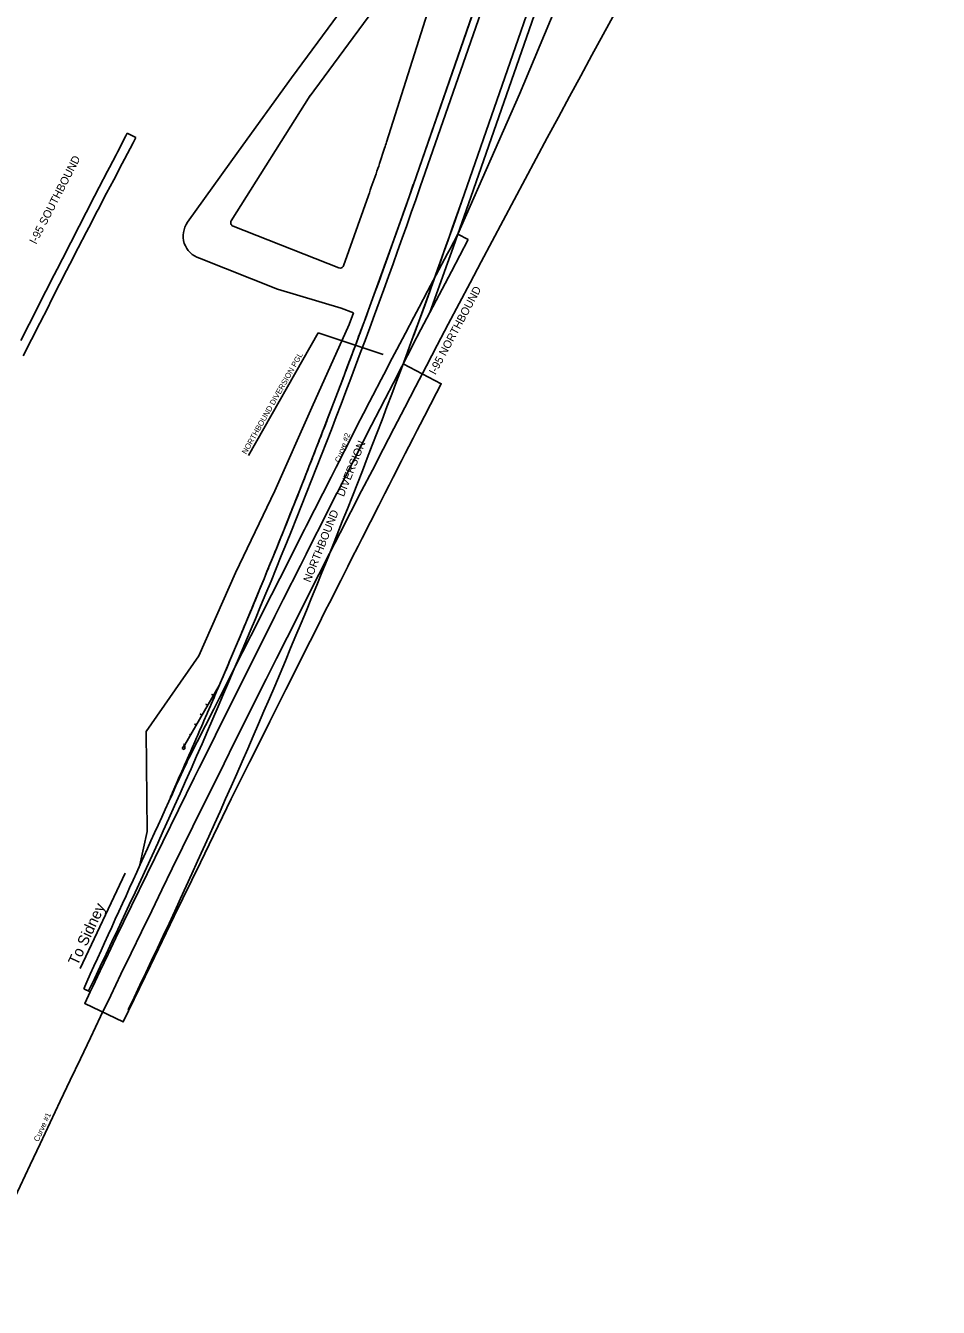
# Model space of a CAD drawing. Extents: x 1160458 to 1162290, y 615427 to 618737.
# Drawn here: x 1160710 to 1161210, y 615879 to 616580 of the extents above; entities that cross this region are included whole.
import ezdxf

# ---------------------------------------------------------------- set-up
doc = ezdxf.new("R2010")
doc.units = 0
for name, color, linetype in [('1', 7, 'Continuous'), ('ANNOTATION', 7, 'Continuous'), ('D_Drainage_Ditch_Line', 7, 'Continuous'), ('D_Guardrail_Beam_Lt', 7, 'Continuous'), ('D_Guardrail_End_MELT', 7, 'Continuous'), ('D_Roadway_Edge_Pavement', 7, 'Continuous'), ('D_Roadway_Edge_Shoulder', 7, 'Continuous'), ('D_Roadway_Edge_TW', 7, 'Continuous'), ('D_Slope_Cut', 7, 'Continuous'), ('D_Slope_Fill', 7, 'Continuous'), ('D_Text_Standard', 7, 'Continuous'), ('Old pavement area_not used', 7, 'Continuous'), ('Shoulder work for div plan (NB)', 7, 'Continuous'), ('Shoulder work for div plans (SB)', 7, 'Continuous')]:
    doc.layers.add(name, color=color, linetype=linetype)

msp = doc.modelspace()

# ---------------------------------------------------------------- linework, layer by layer
at = {"layer": '1'}
msp.add_arc((1171291.23, 610981.4), 11690.13, 149.585749, 157.64029, dxfattribs=at)
at = {"layer": 'D_Drainage_Ditch_Line'}
for p, q in [((1160865.58, 616541.07), (1160946.69, 616651.23)), ((1160822.97, 616473.58), (1160866.18, 616541.95)), ((1160881.78, 616447.76), (1160823.93, 616470.65))]:
    msp.add_line(p, q, dxfattribs=at)
msp.add_lwpolyline([(1160950.21, 616649.43), (1160936.96, 616608.03), (1160936.24, 616605.79), (1160907.92, 616516.58), (1160907.66, 616515.75), (1160907.4, 616514.93), (1160907.13, 616514.12), (1160906.87, 616513.29), (1160904.13, 616504.89), (1160903.65, 616503.46), (1160903.18, 616502.05), (1160902.69, 616500.64), (1160902.19, 616499.21), (1160900.09, 616493.32), (1160899.57, 616491.83), (1160899.04, 616490.35), (1160898.51, 616488.87), (1160897.99, 616487.38), (1160884.4, 616448.95)], dxfattribs=at)
for centre, start, end in [((1160824.66, 616472.51), 147.7107, 248.40964), ((1160882.51, 616449.62), 248.40964, 340.52546)]:
    msp.add_arc(centre, 2, start, end, dxfattribs=at)
at = {"layer": 'D_Guardrail_Beam_Lt'}
msp.add_line((1160966.79, 616620.56), (1160922.58, 616493.37), dxfattribs=at)
for start, end in [(337.73067, 340.83052), (336.81172, 337.73067)]:
    msp.add_arc((1156970.57, 617867.25), 4184, start, end, dxfattribs=at)
at = {"layer": 'D_Guardrail_End_MELT'}
for p, q in [((1160816.43, 616219.44), (1160797.64, 616186.98)), ((1160812.55, 616214.74), (1160812.3, 616214.31)), ((1160812.86, 616214.28), (1160812.43, 616214.53)), ((1160812.99, 616214.49), (1160812.74, 616214.06)), ((1160813.29, 616214.03), (1160812.86, 616214.28)), ((1160809.42, 616209.33), (1160809.17, 616208.9)), ((1160809.73, 616208.87), (1160809.3, 616209.12)), ((1160809.86, 616209.08), (1160809.61, 616208.65)), ((1160810.16, 616208.62), (1160809.73, 616208.87)), ((1160806.29, 616203.93), (1160806.04, 616203.49)), ((1160806.6, 616203.46), (1160806.17, 616203.71)), ((1160806.73, 616203.68), (1160806.47, 616203.24)), ((1160807.03, 616203.21), (1160806.6, 616203.46)), ((1160800.46, 616192.86), (1160800.21, 616192.42)), ((1160803.16, 616198.52), (1160802.91, 616198.08)), ((1160803.47, 616198.05), (1160803.04, 616198.3)), ((1160803.59, 616198.27), (1160803.34, 616197.83)), ((1160803.9, 616197.8), (1160803.47, 616198.05)), ((1160797.17, 616186.67), (1160796.15, 616184.91)), ((1160797.33, 616187.45), (1160797.08, 616187.01)), ((1160797.61, 616186.42), (1160797.17, 616186.67)), ((1160797.64, 616186.98), (1160797.21, 616187.23)), ((1160797.64, 616186.98), (1160797.39, 616186.55)), ((1160797.5, 616184.86), (1160797.61, 616186.42)), ((1160800.77, 616192.39), (1160800.34, 616192.64)), ((1160796.15, 616184.91), (1160797.29, 616184.4)), ((1160797.29, 616184.4), (1160797.5, 616184.86))]:
    msp.add_line(p, q, dxfattribs=at)
at = {"layer": 'D_Roadway_Edge_Pavement'}
for points in [[(1160931.52, 616423.31), (1160941.33, 616450.36), (1160943.46, 616456.34), (1160948.03, 616469.28), (1160952.78, 616482.87), (1160997, 616610.06), (1161003.26, 616627.89), (1161003.93, 616629.76), (1161007.3, 616639.13)], [(1160896.39, 616420.21), (1160911.22, 616461.1), (1160913.34, 616467.05), (1160917.87, 616479.89), (1160922.59, 616493.37), (1160966.8, 616620.56)]]:
    msp.add_lwpolyline(points, dxfattribs=at)
at = {"layer": 'D_Roadway_Edge_Shoulder'}
for p, q in [((1160802.68, 616168.92), (1160759.81, 616081.43)), ((1160745.86, 616051.99), (1160742.23, 616053.64))]:
    msp.add_line(p, q, dxfattribs=at)
msp.add_lwpolyline([(1160789.59, 616158.2), (1160790.43, 616160.09), (1160790.56, 616160.37), (1160790.68, 616160.65), (1160790.81, 616160.94), (1160793.39, 616166.73), (1160794.18, 616168.5), (1160795.39, 616171.24), (1160795.89, 616172.37), (1160796.63, 616174.02), (1160797.47, 616175.92), (1160798.36, 616177.94), (1160798.45, 616178.15), (1160799.59, 616180.72), (1160799.81, 616181.22), (1160800.01, 616181.69), (1160800.42, 616182.61), (1160802.03, 616186.29), (1160802.48, 616187.29), (1160803.63, 616189.94), (1160804.04, 616190.87), (1160804.46, 616191.82), (1160806.05, 616195.47), (1160806.47, 616196.43), (1160806.48, 616196.46), (1160807.81, 616199.52), (1160808.05, 616200.07), (1160809.61, 616203.67), (1160809.81, 616204.12), (1160810.04, 616204.66), (1160811.59, 616208.25), (1160811.79, 616208.71), (1160812.04, 616209.27), (1160813.57, 616212.82), (1160814.02, 616213.87), (1160815.53, 616217.4), (1160815.76, 616217.91), (1160816, 616218.48), (1160817.5, 616221.98), (1160817.97, 616223.09), (1160819.45, 616226.56), (1160819.7, 616227.13), (1160819.94, 616227.71), (1160821.4, 616231.14), (1160821.9, 616232.32), (1160823.35, 616235.72), (1160823.62, 616236.36), (1160823.86, 616236.95), (1160825.29, 616240.31), (1160825.82, 616241.57), (1160826.4, 616242.96), (1160827.22, 616244.9), (1160827.76, 616246.19), (1160829.15, 616249.49), (1160829.46, 616250.23), (1160829.71, 616250.82), (1160830.29, 616252.21), (1160831.07, 616254.08), (1160831.64, 616255.46), (1160832.98, 616258.67), (1160833.58, 616260.09), (1160833.81, 616260.65), (1160834.15, 616261.47), (1160835.03, 616263.59), (1160835.18, 616263.95), (1160836.16, 616266.31), (1160838.04, 616270.85), (1160838.87, 616272.87), (1160839.02, 616273.23), (1160840.9, 616277.81), (1160842.69, 616282.16), (1160842.83, 616282.51), (1160843.07, 616283.1), (1160843.78, 616284.84), (1160846.01, 616290.29), (1160846.81, 616292.28), (1160846.86, 616292.4), (1160847.68, 616294.41), (1160848.6, 616296.68), (1160848.86, 616297.32), (1160849.45, 616298.79), (1160849.59, 616299.12), (1160850.75, 616301.99), (1160851.48, 616303.82), (1160852.62, 616306.65), (1160853.21, 616308.12), (1160853.38, 616308.54), (1160854.5, 616311.33), (1160855.27, 616313.24), (1160855.96, 616314.99), (1160856.38, 616316.02), (1160857.15, 616317.96), (1160858.24, 616320.69), (1160859.31, 616323.37), (1160859.69, 616324.34), (1160860.11, 616325.39), (1160860.9, 616327.41), (1160861.96, 616330.06), (1160862.99, 616332.68), (1160863.4, 616333.71), (1160863.81, 616334.76), (1160864.83, 616337.35), (1160865.65, 616339.45), (1160866.49, 616341.58), (1160867.22, 616343.45), (1160867.35, 616343.78), (1160867.49, 616344.14), (1160868.48, 616346.66), (1160869.32, 616348.84), (1160871, 616353.16), (1160871.15, 616353.54), (1160872.1, 616355.99), (1160872.97, 616358.23), (1160873.91, 616360.66), (1160874.64, 616362.56), (1160874.79, 616362.94), (1160874.99, 616363.48), (1160875.68, 616365.26), (1160876.6, 616367.64), (1160877.5, 616369.99), (1160878.4, 616372.34), (1160878.6, 616372.87), (1160879.32, 616374.74), (1160880.2, 616377.06), (1160881.13, 616379.5), (1160882, 616381.78), (1160882.2, 616382.31), (1160882.94, 616384.27), (1160883.79, 616386.5), (1160884.4, 616388.14), (1160884.74, 616389.02), (1160885.3, 616390.5), (1160885.57, 616391.23), (1160886.53, 616393.77), (1160887.35, 616395.94), (1160888.33, 616398.55), (1160889.12, 616400.68), (1160889.91, 616402.78), (1160890.89, 616405.41), (1160891.89, 616408.09), (1160892.04, 616408.5), (1160892.66, 616410.17), (1160893.41, 616412.19), (1160894.42, 616414.9), (1160895.43, 616417.65), (1160896.01, 616419.2), (1160896.18, 616419.67), (1160896.9, 616421.62)], dxfattribs=at)
at = {"layer": 'D_Roadway_Edge_TW'}
for points in [[(1160926.36, 616492.06), (1160970.57, 616619.24)], [(1160922.64, 616410.51), (1160937.59, 616451.71), (1160939.71, 616457.68), (1160944.28, 616470.6), (1160949.03, 616484.18), (1160993.24, 616611.37)]]:
    msp.add_lwpolyline(points, dxfattribs=at)
for radius in [4188, 4212]:
    msp.add_arc((1156970.57, 617867.25), radius, 334.32021, 340.83052, dxfattribs=at)
at = {"layer": 'D_Slope_Cut'}
for p, q in [((1160799.1, 616472.73), (1160827, 616511.63)), ((1160889.91, 616423.11), (1160883.02, 616425.76))]:
    msp.add_line(p, q, dxfattribs=at)
for points in [[(1160827, 616511.63), (1160855.92, 616551.61), (1160946.84, 616675.03)], [(1160883.02, 616425.76), (1160848.32, 616436.22), (1160805.63, 616453.11)]]:
    msp.add_lwpolyline(points, dxfattribs=at)
msp.add_ellipse((1160809.19, 616465.24), major_axis=(-2.28, -12.43), ratio=0.992486, start_param=4.257747, end_param=6.178773, dxfattribs=at)
at = {"layer": 'D_Slope_Fill'}
msp.add_line((1160887.47, 616416.78), (1160889.91, 616423.11), dxfattribs=at)
for points in [[(1160946.97, 616466.26), (1160980.7, 616542.71), (1160999.92, 616588.93), (1161022.85, 616633.52), (1161041.25, 616679.39), (1161054.56, 616727.27), (1161073.15, 616773.14), (1161093.34, 616818.32), (1161115.32, 616850.38), (1161120.44, 616842.97), (1161125.37, 616846.38), (1161120.26, 616853.78), (1161114.5, 616863.05), (1161132.51, 616909.29), (1161143.14, 616931.66)], [(1160772.89, 616121.38), (1160776.99, 616139.57), (1160776.39, 616194.19), (1160805.21, 616235.72), (1160825.34, 616281.08), (1160846.82, 616325.94), (1160866.97, 616371.39), (1160887.47, 616416.78)]]:
    msp.add_lwpolyline(points, dxfattribs=at)
at = {"layer": 'D_Text_Standard'}
for p, q in [((1160832.37, 616345.16), (1160870.45, 616412.29)), ((1160870.45, 616412.29), (1160906.16, 616400.4)), ((1160764.89, 616116.86), (1160740.31, 616064.67))]:
    msp.add_line(p, q, dxfattribs=at)
at = {"layer": 'Old pavement area_not used'}
for p, q in [((1160799.06, 616178.44), (1160796.62, 616173.1)), ((1160791.77, 616093.28), (1160806.13, 616122.65)), ((1160742.23, 616053.64), (1160745.86, 616051.99))]:
    msp.add_line(p, q, dxfattribs=at)
for points in [[(1160946.97, 616466.26), (1160942.65, 616458.19), (1160941.24, 616455.56), (1160936.55, 616446.73), (1160935.09, 616443.97), (1160930.41, 616435.13), (1160925.74, 616426.28), (1160922.91, 616420.9), (1160918.24, 616412.06), (1160913.58, 616403.21), (1160911.03, 616398.37), (1160906.39, 616389.51), (1160904.97, 616386.79), (1160900.36, 616377.92), (1160898.65, 616374.62), (1160895.35, 616368.23), (1160891.94, 616361.6), (1160887.39, 616352.69), (1160884.87, 616347.74), (1160880.33, 616338.83), (1160877.58, 616333.4), (1160873.06, 616324.48), (1160868.55, 616315.56), (1160864.03, 616306.64), (1160863.07, 616304.73), (1160858.56, 616295.8), (1160854.04, 616286.88), (1160849.53, 616277.96), (1160845.02, 616269.03), (1160840.51, 616260.11), (1160836, 616251.18), (1160833.67, 616246.56), (1160829.16, 616237.64), (1160824.65, 616228.71), (1160820.9, 616221.31), (1160816.38, 616212.39), (1160813.36, 616206.44), (1160808.82, 616197.53), (1160804.27, 616188.63), (1160799.06, 616178.44)], [(1160931.52, 616423.3), (1160941.33, 616450.36), (1160943.46, 616456.34), (1160946.97, 616466.26)], [(1160806.13, 616122.65), (1160822.95, 616157.43), (1160832.95, 616177.53), (1160839.62, 616190.88), (1160844.09, 616199.83), (1160848.57, 616208.77), (1160852.85, 616217.31), (1160857.34, 616226.25), (1160861.63, 616234.78), (1160866.12, 616243.72), (1160870.27, 616251.95), (1160874.43, 616260.18), (1160876.68, 616264.65), (1160882.83, 616276.82), (1160886.74, 616284.53), (1160888.99, 616288.99), (1160892.33, 616295.57), (1160894.6, 616300.03), (1160899.12, 616308.95), (1160903.66, 616317.86), (1160907.01, 616324.44), (1160909.28, 616328.9), (1160911.55, 616333.35), (1160916.1, 616342.26), (1160918.13, 616346.23), (1160920.16, 616350.2), (1160922.45, 616354.65), (1160924.73, 616359.1), (1160926.31, 616362.18), (1160928.61, 616366.62), (1160935.23, 616379.45), (1160937.82, 616384.43), (1160916.99, 616395.24), (1160921.57, 616404.13), (1160922.16, 616405.26), (1160926.76, 616414.14), (1160931.52, 616423.3)], [(1160796.62, 616173.1), (1160794.67, 616168.81), (1160792.72, 616164.52), (1160790.77, 616160.23), (1160788.81, 616155.95), (1160786.86, 616151.66), (1160784.91, 616147.37), (1160782.96, 616143.08), (1160781.01, 616138.79), (1160779.05, 616134.51), (1160777.1, 616130.22), (1160775.15, 616125.93), (1160773.2, 616121.64), (1160771.24, 616117.36), (1160769.29, 616113.07), (1160767.34, 616108.78), (1160765.39, 616104.49), (1160763.43, 616100.2), (1160761.48, 616095.92), (1160759.53, 616091.63), (1160757.58, 616087.34), (1160755.62, 616083.05), (1160753.67, 616078.77), (1160751.72, 616074.48), (1160749.77, 616070.19), (1160747.81, 616065.9), (1160745.86, 616061.61), (1160743.91, 616057.33), (1160742.23, 616053.64)], [(1160745.86, 616051.99), (1160742.78, 616045.5), (1160763.9, 616035.49), (1160778.74, 616066.26), (1160791.77, 616093.28)]]:
    msp.add_lwpolyline(points, dxfattribs=at)
at = {"layer": 'Shoulder work for div plan (NB)'}
for p, q in [((1160946.97, 616466.26), (1160942.65, 616458.19)), ((1160952.63, 616463.25), (1160946.97, 616466.26)), ((1160941.24, 616455.56), (1160936.55, 616446.73)), ((1160942.65, 616458.19), (1160941.24, 616455.56)), ((1160936.55, 616446.73), (1160935.09, 616443.97)), ((1160925.74, 616426.28), (1160922.91, 616420.9)), ((1160922.91, 616420.9), (1160918.24, 616412.06)), ((1160918.24, 616412.06), (1160913.58, 616403.21)), ((1160913.58, 616403.21), (1160911.03, 616398.37)), ((1160921.57, 616404.13), (1160922.16, 616405.26)), ((1160911.03, 616398.37), (1160906.39, 616389.51)), ((1160906.39, 616389.51), (1160904.97, 616386.79)), ((1160904.97, 616386.79), (1160900.36, 616377.92)), ((1160900.36, 616377.92), (1160898.65, 616374.62)), ((1160898.65, 616374.62), (1160895.35, 616368.23)), ((1160884.87, 616347.74), (1160880.33, 616338.83)), ((1160887.39, 616352.69), (1160884.87, 616347.74)), ((1160877.58, 616333.4), (1160873.06, 616324.48)), ((1160880.33, 616338.83), (1160877.58, 616333.4)), ((1160873.06, 616324.48), (1160868.55, 616315.56)), ((1160868.55, 616315.56), (1160864.03, 616306.64)), ((1160858.56, 616295.8), (1160854.04, 616286.88)), ((1160854.04, 616286.88), (1160849.53, 616277.96)), ((1160840.51, 616260.11), (1160836, 616251.18)), ((1160836, 616251.18), (1160833.67, 616246.56)), ((1160833.67, 616246.56), (1160829.16, 616237.64)), ((1160829.16, 616237.64), (1160824.65, 616228.71)), ((1160824.65, 616228.71), (1160820.9, 616221.31)), ((1160820.9, 616221.31), (1160816.38, 616212.39)), ((1160808.82, 616197.53), (1160804.27, 616188.63)), ((1160804.27, 616188.63), (1160799.71, 616179.72)), ((1160799.71, 616179.72), (1160799.06, 616178.44)), ((1160796.62, 616173.1), (1160794.67, 616168.81)), ((1160798.58, 616177.39), (1160796.62, 616173.1)), ((1160799.06, 616178.44), (1160798.58, 616177.39)), ((1160759.81, 616081.43), (1160802.68, 616168.92)), ((1160794.67, 616168.81), (1160792.72, 616164.52)), ((1160790.77, 616160.23), (1160788.81, 616155.95)), ((1160792.72, 616164.52), (1160790.77, 616160.23)), ((1160788.81, 616155.95), (1160786.86, 616151.66)), ((1160781.01, 616138.79), (1160779.05, 616134.51)), ((1160782.96, 616143.08), (1160781.01, 616138.79)), ((1160775.15, 616125.93), (1160773.2, 616121.64)), ((1160771.24, 616117.36), (1160769.29, 616113.07)), ((1160773.2, 616121.64), (1160771.24, 616117.36)), ((1160767.34, 616108.78), (1160765.39, 616104.49)), ((1160769.29, 616113.07), (1160767.34, 616108.78)), ((1160765.39, 616104.49), (1160763.43, 616100.2)), ((1160761.48, 616095.92), (1160759.53, 616091.63)), ((1160763.43, 616100.2), (1160761.48, 616095.92)), ((1160755.62, 616083.05), (1160753.67, 616078.77)), ((1160753.67, 616078.77), (1160751.72, 616074.48)), ((1160743.91, 616057.33), (1160742.23, 616053.64)), ((1160742.23, 616053.64), (1160745.86, 616051.99))]:
    msp.add_line(p, q, dxfattribs=at)
for points in [[(1160931.52, 616423.3), (1160943.37, 616445.84), (1160952.63, 616463.25)], [(1160935.09, 616443.97), (1160930.41, 616435.13), (1160925.74, 616426.28)], [(1160922.16, 616405.26), (1160926.76, 616414.14), (1160931.52, 616423.3)], [(1160802.68, 616168.92), (1160805.45, 616174.46), (1160809.92, 616183.4), (1160814.39, 616192.35), (1160815.87, 616195.31), (1160820.34, 616204.25), (1160824.81, 616213.2), (1160829.27, 616222.15), (1160833.74, 616231.1), (1160836.93, 616237.49), (1160841.39, 616246.44), (1160845.86, 616255.38), (1160846.89, 616257.42), (1160851.36, 616266.37), (1160855.85, 616275.3), (1160856.3, 616276.2), (1160860.79, 616285.13), (1160863.87, 616291.24), (1160868.38, 616300.17), (1160871.7, 616306.72), (1160876.23, 616315.64), (1160880.76, 616324.55), (1160881.1, 616325.21), (1160885.64, 616334.12), (1160890.19, 616343.02), (1160894.74, 616351.93), (1160895.18, 616352.79), (1160899.74, 616361.69), (1160904.31, 616370.59), (1160907.13, 616376.09), (1160911.71, 616384.98), (1160916.28, 616393.87), (1160916.99, 616395.24), (1160921.57, 616404.13)], [(1160895.35, 616368.23), (1160891.94, 616361.6), (1160887.39, 616352.69)], [(1160864.03, 616306.64), (1160863.07, 616304.73), (1160858.56, 616295.8)], [(1160849.53, 616277.96), (1160845.02, 616269.03), (1160840.51, 616260.11)], [(1160816.38, 616212.39), (1160813.36, 616206.44), (1160808.82, 616197.53)], [(1160786.86, 616151.66), (1160784.91, 616147.37), (1160782.96, 616143.08)], [(1160779.05, 616134.51), (1160777.1, 616130.22), (1160775.15, 616125.93)], [(1160759.53, 616091.63), (1160757.58, 616087.34), (1160755.62, 616083.05)], [(1160745.86, 616051.99), (1160747.01, 616054.42), (1160751.29, 616063.45), (1160755.57, 616072.49), (1160759.81, 616081.43)], [(1160751.72, 616074.48), (1160749.77, 616070.19), (1160747.81, 616065.9)], [(1160747.81, 616065.9), (1160745.86, 616061.61), (1160743.91, 616057.33)]]:
    msp.add_lwpolyline(points, dxfattribs=at)
at = {"layer": 'Shoulder work for div plans (SB)'}
for p, q in [((1160770.78, 616519.03), (1160766.08, 616521.48)), ((1160770.77, 616519.01), (1160770.78, 616519.03)), ((1160727.7, 616447.07), (1160727.7, 616447.07))]:
    msp.add_line(p, q, dxfattribs=at)
for points in [[(1160709.05, 616399.66), (1160713.61, 616408.56), (1160718.17, 616417.47), (1160722.72, 616426.37), (1160724.52, 616429.93), (1160729.06, 616438.84), (1160732.9, 616446.34), (1160734.67, 616449.79), (1160739.25, 616458.68), (1160743.84, 616467.56), (1160745.03, 616469.86), (1160749.64, 616478.74), (1160750.14, 616479.7), (1160754.76, 616488.56), (1160758.66, 616495.99), (1160763.31, 616504.84), (1160764.6, 616507.28), (1160769.25, 616516.13), (1160770.77, 616519.01)], [(1160766.08, 616521.48), (1160766.07, 616521.46), (1160765.32, 616520.02), (1160760.7, 616511.14), (1160759.92, 616509.63), (1160756.35, 616502.74)], [(1160756.35, 616502.74), (1160755.32, 616500.75), (1160750.73, 616491.87), (1160748.22, 616487.01), (1160743.64, 616478.12), (1160739.77, 616470.59), (1160735.2, 616461.7), (1160730.64, 616452.8), (1160727.7, 616447.07)], [(1160727.7, 616447.07), (1160726.09, 616443.92), (1160721.54, 616435.02), (1160721.43, 616434.81), (1160716.88, 616425.9), (1160712.33, 616416.99), (1160707.79, 616408.09)]]:
    msp.add_lwpolyline(points, dxfattribs=at)

# ---------------------------------------------------------------- texts
at = {"layer": 'ANNOTATION'}
for s, rotation, p in [('Curve #2', 69.7081, (1160882.33, 616341.1)), ('Curve #1', 65.03597, (1160717.43, 615969.74))]:
    msp.add_text(s, height=3, rotation=rotation, dxfattribs=at).set_placement(p)
at = {"layer": 'D_Text_Standard'}
for s, height, rotation, p in [('I-95 SOUTHBOUND', 4.375, 62.75995, (1160716.16, 616460.36)), ('I-95 NORTHBOUND', 4.375, 61.86733, (1160934.63, 616388.98)), ('NORTHBOUND DIVERSION PGL', 3, 60.4348, (1160831.17, 616345.58)), ('DIVERSION', 4.375, 68.16263, (1160884.52, 616322.33)), ('NORTHBOUND', 4.375, 68.16263, (1160866.22, 616275.46)), ('To Sidney', 6, 64.9584, (1160738.89, 616065.91))]:
    msp.add_text(s, height=height, rotation=rotation, dxfattribs=at).set_placement(p)

doc.saveas('drawing.dxf')
